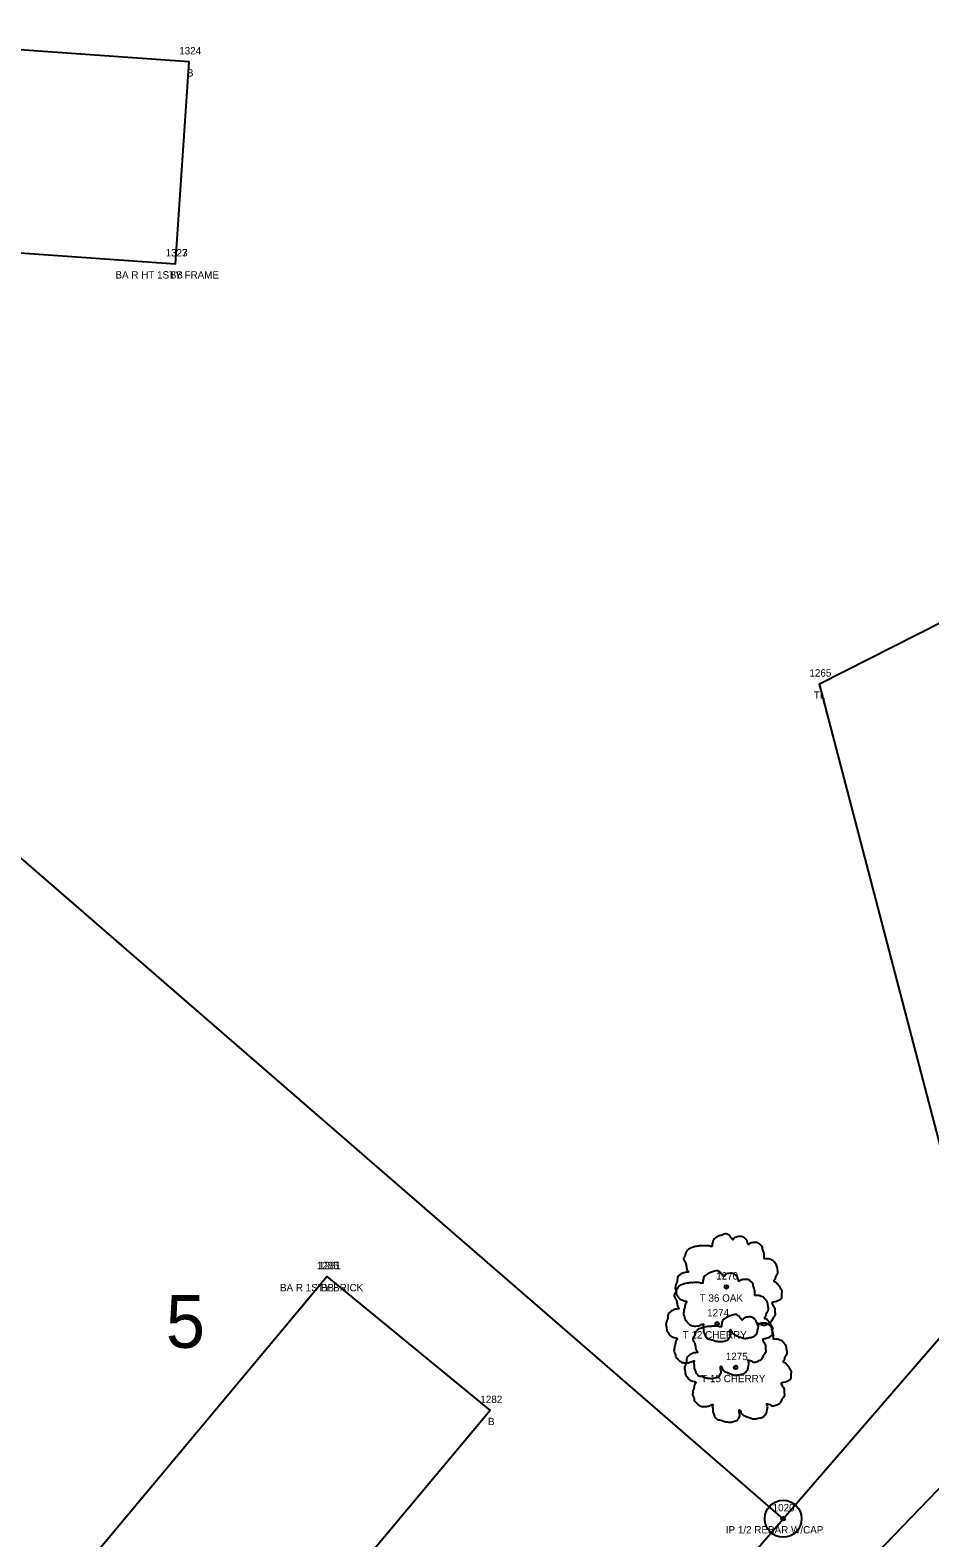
# Model space of a CAD drawing. Extents: x 1812113 to 1819860, y 1177395 to 1181185.
# Drawn here: x 1813774.2 to 1813896.2, y 1178275.6 to 1178480 of the extents above; entities that cross this region are included whole.
import ezdxf

# ---------------------------------------------------------------- set-up
doc = ezdxf.new("R2010")
doc.units = 0
for name, color, linetype in [('RD_EX_Bldg', 7, 'Continuous'), ('RD_EX_Bldg_txCode', 7, 'Continuous'), ('RD_EX_DV_Prop', 7, 'Continuous'), ('RD_EX_DV_Prop_txCode', 7, 'Continuous'), ('RD_EX_DV_PropPin', 7, 'Continuous'), ('RD_EX_DV_TX_Prop', 7, 'Continuous'), ('RD_EX_Road', 7, 'Continuous'), ('RD_EX_VEG', 7, 'Continuous'), ('RD_EX_VEG_txCode', 7, 'Continuous'), ('RD_SMD_Locator', 7, 'Continuous')]:
    doc.layers.add(name, color=color, linetype=linetype)

msp = doc.modelspace()

# ---------------------------------------------------------------- linework, layer by layer
at = {"layer": 'RD_EX_Bldg'}
for points in [[(1813793.91, 1178448.32), (1813795.75, 1178475.7), (1813735.04, 1178479.99), (1813733.19, 1178452.61), (1813793.91, 1178448.32)], [(1813814.41, 1178311.05), (1813836.59, 1178292.91), (1813805.22, 1178255.39), (1813783.05, 1178273.53), (1813814.41, 1178311.05)]]:
    msp.add_lwpolyline(points, dxfattribs=at)
at = {"layer": 'RD_EX_DV_Prop'}
for p, q in [((1813876.31, 1178278.23), (1814007.16, 1178429.49)), ((1813876.31, 1178278.23), (1813762.97, 1178376.42)), ((1813820.68, 1178213.93), (1813876.31, 1178278.23))]:
    msp.add_line(p, q, dxfattribs=at)
at = {"layer": 'RD_EX_DV_PropPin'}
for radius in [2.5, 0.25]:
    msp.add_circle((1813876.31, 1178278.23), radius, dxfattribs=at)
at = {"layer": 'RD_EX_Road'}
msp.add_line((1813874.69, 1178258.74), (1813910.02, 1178295.38), dxfattribs=at)
at = {"layer": 'RD_EX_VEG'}
msp.add_lwpolyline([(1813961.33, 1178431.97), (1813986.04, 1178406.55), (1813953.31, 1178366.71), (1813903.24, 1178307.28), (1813881.24, 1178391.37), (1813961.33, 1178431.97)], dxfattribs=at)
for centre, radius in [((1813868.62, 1178309.64), 0.25), ((1813868.61, 1178309.62), 0.0001), ((1813867.35, 1178304.65), 0.25), ((1813867.34, 1178304.63), 0.0001), ((1813869.87, 1178298.73), 0.25), ((1813869.86, 1178298.71), 0.0001)]:
    msp.add_circle(centre, radius, dxfattribs=at)
for points in [[(1813868.75, 1178316.81), (1813868.45, 1178316.83), (1813868.13, 1178316.73), (1813867.88, 1178316.63), (1813867.65, 1178316.56), (1813867.43, 1178316.46), (1813867.13, 1178316.28), (1813866.9, 1178316.08), (1813866.78, 1178315.83), (1813866.73, 1178315.61), (1813866.68, 1178315.33), (1813866.68, 1178315.16), (1813866.55, 1178315.13), (1813866.4, 1178315.16), (1813866.15, 1178315.23), (1813865.9, 1178315.23), (1813865.65, 1178315.23), (1813865.3, 1178315.21), (1813864.95, 1178315.21), (1813864.68, 1178315.16), (1813864.35, 1178315.11), (1813863.98, 1178314.98), (1813863.63, 1178314.86), (1813863.33, 1178314.61), (1813863.08, 1178314.13), (1813862.96, 1178313.78), (1813862.81, 1178313.53), (1813862.96, 1178313.08), (1813863.13, 1178312.73), (1813863.15, 1178312.53), (1813863.23, 1178312.11), (1813863.33, 1178311.88), (1813863.45, 1178311.68), (1813863.38, 1178311.66), (1813863.01, 1178311.61), (1813862.71, 1178311.51), (1813862.28, 1178311.28), (1813862.06, 1178311.06), (1813861.96, 1178310.73), (1813861.93, 1178310.38), (1813861.83, 1178310.18), (1813861.76, 1178309.91), (1813861.73, 1178309.83), (1813861.68, 1178309.51), (1813861.78, 1178309.06), (1813861.81, 1178308.71), (1813861.93, 1178308.49), (1813862.08, 1178308.31), (1813862.26, 1178308.06), (1813862.66, 1178307.84), (1813862.98, 1178307.74), (1813863.18, 1178307.71), (1813863.01, 1178307.21), (1813862.96, 1178306.86), (1813862.83, 1178306.46), (1813862.83, 1178306.39), (1813862.78, 1178305.91), (1813862.93, 1178305.59), (1813863.01, 1178305.21), (1813863.18, 1178304.99), (1813863.45, 1178304.69), (1813863.78, 1178304.46), (1813864.28, 1178304.34), (1813864.68, 1178304.36), (1813865.25, 1178304.54), (1813865.5, 1178304.61), (1813865.48, 1178304.44), (1813865.5, 1178304.06), (1813865.5, 1178303.64), (1813865.65, 1178303.31), (1813865.75, 1178303.04), (1813865.9, 1178302.79), (1813866.23, 1178302.56), (1813866.63, 1178302.49), (1813867.05, 1178302.34), (1813867.5, 1178302.26), (1813868, 1178302.24), (1813868.6, 1178302.39), (1813868.88, 1178302.51), (1813868.98, 1178302.69), (1813869.18, 1178303.06), (1813869.13, 1178303.29), (1813869.15, 1178303.89), (1813869.25, 1178303.71), (1813869.43, 1178303.36), (1813869.93, 1178303.06), (1813870.33, 1178302.89), (1813870.8, 1178302.74), (1813871.1, 1178302.66), (1813871.58, 1178302.74), (1813871.95, 1178302.81), (1813872.33, 1178302.94), (1813872.63, 1178303.21), (1813872.8, 1178303.49), (1813872.85, 1178303.76), (1813872.93, 1178304.14), (1813872.98, 1178304.31)], [(1813872.98, 1178304.31), (1813872.9, 1178304.49), (1813872.85, 1178304.74), (1813872.93, 1178304.71), (1813873.1, 1178304.66), (1813873.38, 1178304.54), (1813873.6, 1178304.46), (1813873.93, 1178304.49), (1813874.2, 1178304.59), (1813874.65, 1178304.86), (1813874.92, 1178305.34), (1813875.2, 1178305.74), (1813875.27, 1178306.06), (1813875.22, 1178306.29), (1813875.2, 1178306.79), (1813875, 1178307.04), (1813874.95, 1178307.16), (1813874.85, 1178307.56), (1813874.92, 1178307.61), (1813875.2, 1178307.66), (1813875.57, 1178307.79), (1813875.85, 1178307.91), (1813876.07, 1178308.09), (1813876.15, 1178308.31), (1813876.12, 1178308.71), (1813876.17, 1178309.11), (1813876.1, 1178309.26), (1813876, 1178309.41), (1813875.92, 1178309.61), (1813875.77, 1178309.76), (1813875.67, 1178309.91), (1813875.57, 1178310.01), (1813875.45, 1178310.16), (1813875.27, 1178310.28), (1813875.12, 1178310.33), (1813875.07, 1178310.48), (1813875.22, 1178310.68), (1813875.27, 1178310.78), (1813875.3, 1178311.01), (1813875.52, 1178311.36), (1813875.57, 1178311.76), (1813875.52, 1178312.18), (1813875.47, 1178312.46), (1813875.32, 1178312.73), (1813875.12, 1178312.98), (1813875, 1178313.16), (1813874.82, 1178313.28), (1813874.5, 1178313.41), (1813874.25, 1178313.46), (1813873.9, 1178313.46), (1813873.7, 1178313.51), (1813873.73, 1178313.56), (1813873.73, 1178313.71), (1813873.73, 1178313.98), (1813873.65, 1178314.43), (1813873.5, 1178314.93), (1813873.5, 1178314.96), (1813873.4, 1178315.21), (1813873.18, 1178315.41), (1813873, 1178315.51), (1813872.8, 1178315.63), (1813872.55, 1178315.66), (1813872.25, 1178315.66), (1813871.98, 1178315.61), (1813871.78, 1178315.51), (1813871.6, 1178315.38), (1813871.53, 1178315.53), (1813871.43, 1178315.83), (1813871.38, 1178315.98), (1813871.23, 1178316.16), (1813871, 1178316.36), (1813870.55, 1178316.48), (1813869.93, 1178316.41), (1813869.63, 1178316.21), (1813869.48, 1178316.03), (1813869.43, 1178316.16), (1813869.23, 1178316.36), (1813869.13, 1178316.53), (1813868.95, 1178316.66), (1813868.8, 1178316.76), (1813868.7, 1178316.81)], [(1813867.48, 1178311.82), (1813867.18, 1178311.84), (1813866.86, 1178311.74), (1813866.61, 1178311.64), (1813866.38, 1178311.57), (1813866.16, 1178311.47), (1813865.86, 1178311.29), (1813865.63, 1178311.09), (1813865.51, 1178310.84), (1813865.46, 1178310.62), (1813865.41, 1178310.34), (1813865.41, 1178310.17), (1813865.28, 1178310.14), (1813865.13, 1178310.17), (1813864.88, 1178310.24), (1813864.63, 1178310.24), (1813864.38, 1178310.24), (1813864.03, 1178310.22), (1813863.68, 1178310.22), (1813863.41, 1178310.17), (1813863.08, 1178310.12), (1813862.71, 1178309.99), (1813862.36, 1178309.87), (1813862.06, 1178309.62), (1813861.81, 1178309.14), (1813861.68, 1178308.79), (1813861.53, 1178308.54), (1813861.68, 1178308.09), (1813861.86, 1178307.74), (1813861.88, 1178307.54), (1813861.96, 1178307.12), (1813862.06, 1178306.89), (1813862.18, 1178306.69), (1813862.11, 1178306.67), (1813861.73, 1178306.62), (1813861.43, 1178306.52), (1813861.01, 1178306.29), (1813860.78, 1178306.07), (1813860.68, 1178305.74), (1813860.66, 1178305.39), (1813860.56, 1178305.19), (1813860.48, 1178304.92), (1813860.46, 1178304.84), (1813860.41, 1178304.52), (1813860.51, 1178304.07), (1813860.53, 1178303.72), (1813860.66, 1178303.5), (1813860.81, 1178303.32), (1813860.98, 1178303.07), (1813861.38, 1178302.85), (1813861.71, 1178302.75), (1813861.91, 1178302.72), (1813861.73, 1178302.22), (1813861.68, 1178301.87), (1813861.56, 1178301.47), (1813861.56, 1178301.4), (1813861.51, 1178300.92), (1813861.66, 1178300.6), (1813861.73, 1178300.22), (1813861.91, 1178300), (1813862.18, 1178299.7), (1813862.51, 1178299.47), (1813863.01, 1178299.35), (1813863.41, 1178299.37), (1813863.98, 1178299.55), (1813864.23, 1178299.62), (1813864.21, 1178299.45), (1813864.23, 1178299.07), (1813864.23, 1178298.65), (1813864.38, 1178298.32), (1813864.48, 1178298.05), (1813864.63, 1178297.8), (1813864.96, 1178297.57), (1813865.36, 1178297.5), (1813865.78, 1178297.35), (1813866.23, 1178297.27), (1813866.73, 1178297.25), (1813867.33, 1178297.4), (1813867.61, 1178297.52), (1813867.71, 1178297.7), (1813867.91, 1178298.07), (1813867.86, 1178298.3), (1813867.88, 1178298.9), (1813867.98, 1178298.72), (1813868.15, 1178298.37), (1813868.65, 1178298.07), (1813869.05, 1178297.9), (1813869.53, 1178297.75), (1813869.83, 1178297.67), (1813870.3, 1178297.75), (1813870.68, 1178297.82), (1813871.05, 1178297.95), (1813871.35, 1178298.22), (1813871.53, 1178298.5), (1813871.58, 1178298.77), (1813871.65, 1178299.15), (1813871.7, 1178299.32)], [(1813871.7, 1178299.32), (1813871.63, 1178299.5), (1813871.58, 1178299.75), (1813871.65, 1178299.72), (1813871.83, 1178299.67), (1813872.1, 1178299.55), (1813872.33, 1178299.47), (1813872.65, 1178299.5), (1813872.93, 1178299.6), (1813873.38, 1178299.87), (1813873.65, 1178300.35), (1813873.93, 1178300.75), (1813874, 1178301.07), (1813873.95, 1178301.3), (1813873.93, 1178301.8), (1813873.73, 1178302.05), (1813873.68, 1178302.17), (1813873.58, 1178302.57), (1813873.65, 1178302.62), (1813873.93, 1178302.67), (1813874.3, 1178302.8), (1813874.58, 1178302.92), (1813874.8, 1178303.1), (1813874.88, 1178303.32), (1813874.85, 1178303.72), (1813874.9, 1178304.12), (1813874.83, 1178304.27), (1813874.73, 1178304.42), (1813874.65, 1178304.62), (1813874.5, 1178304.77), (1813874.4, 1178304.92), (1813874.3, 1178305.02), (1813874.18, 1178305.17), (1813874, 1178305.29), (1813873.85, 1178305.34), (1813873.8, 1178305.49), (1813873.95, 1178305.69), (1813874, 1178305.79), (1813874.03, 1178306.02), (1813874.25, 1178306.37), (1813874.3, 1178306.77), (1813874.25, 1178307.19), (1813874.2, 1178307.47), (1813874.05, 1178307.74), (1813873.85, 1178307.99), (1813873.73, 1178308.17), (1813873.55, 1178308.29), (1813873.23, 1178308.42), (1813872.98, 1178308.47), (1813872.63, 1178308.47), (1813872.43, 1178308.52), (1813872.45, 1178308.57), (1813872.45, 1178308.72), (1813872.45, 1178308.99), (1813872.38, 1178309.44), (1813872.23, 1178309.94), (1813872.23, 1178309.97), (1813872.13, 1178310.22), (1813871.9, 1178310.42), (1813871.73, 1178310.52), (1813871.53, 1178310.64), (1813871.28, 1178310.67), (1813870.98, 1178310.67), (1813870.7, 1178310.62), (1813870.5, 1178310.52), (1813870.33, 1178310.39), (1813870.25, 1178310.54), (1813870.15, 1178310.84), (1813870.1, 1178310.99), (1813869.95, 1178311.17), (1813869.73, 1178311.37), (1813869.28, 1178311.49), (1813868.65, 1178311.42), (1813868.35, 1178311.22), (1813868.2, 1178311.04), (1813868.15, 1178311.17), (1813867.95, 1178311.37), (1813867.86, 1178311.54), (1813867.68, 1178311.67), (1813867.53, 1178311.77), (1813867.43, 1178311.82)], [(1813870.01, 1178305.89), (1813869.71, 1178305.92), (1813869.38, 1178305.82), (1813869.13, 1178305.72), (1813868.91, 1178305.64), (1813868.68, 1178305.54), (1813868.38, 1178305.37), (1813868.16, 1178305.17), (1813868.03, 1178304.92), (1813867.98, 1178304.69), (1813867.93, 1178304.42), (1813867.93, 1178304.25), (1813867.81, 1178304.22), (1813867.66, 1178304.25), (1813867.41, 1178304.32), (1813867.16, 1178304.32), (1813866.91, 1178304.32), (1813866.56, 1178304.3), (1813866.21, 1178304.3), (1813865.93, 1178304.25), (1813865.61, 1178304.2), (1813865.23, 1178304.07), (1813864.88, 1178303.95), (1813864.58, 1178303.7), (1813864.33, 1178303.22), (1813864.21, 1178302.87), (1813864.06, 1178302.62), (1813864.21, 1178302.17), (1813864.38, 1178301.82), (1813864.41, 1178301.62), (1813864.48, 1178301.2), (1813864.58, 1178300.97), (1813864.71, 1178300.77), (1813864.63, 1178300.75), (1813864.26, 1178300.7), (1813863.96, 1178300.6), (1813863.53, 1178300.37), (1813863.31, 1178300.15), (1813863.21, 1178299.82), (1813863.18, 1178299.47), (1813863.08, 1178299.27), (1813863.01, 1178299), (1813862.98, 1178298.92), (1813862.93, 1178298.6), (1813863.03, 1178298.15), (1813863.06, 1178297.8), (1813863.18, 1178297.57), (1813863.33, 1178297.4), (1813863.51, 1178297.15), (1813863.91, 1178296.92), (1813864.23, 1178296.82), (1813864.43, 1178296.8), (1813864.26, 1178296.3), (1813864.21, 1178295.95), (1813864.08, 1178295.55), (1813864.08, 1178295.47), (1813864.03, 1178295), (1813864.18, 1178294.67), (1813864.26, 1178294.3), (1813864.43, 1178294.07), (1813864.71, 1178293.77), (1813865.03, 1178293.55), (1813865.53, 1178293.42), (1813865.93, 1178293.45), (1813866.51, 1178293.62), (1813866.76, 1178293.7), (1813866.73, 1178293.52), (1813866.76, 1178293.15), (1813866.76, 1178292.73), (1813866.91, 1178292.4), (1813867.01, 1178292.13), (1813867.16, 1178291.88), (1813867.48, 1178291.65), (1813867.88, 1178291.58), (1813868.31, 1178291.43), (1813868.76, 1178291.35), (1813869.26, 1178291.33), (1813869.86, 1178291.48), (1813870.13, 1178291.6), (1813870.23, 1178291.78), (1813870.43, 1178292.15), (1813870.38, 1178292.38), (1813870.41, 1178292.98), (1813870.51, 1178292.8), (1813870.68, 1178292.45), (1813871.18, 1178292.15), (1813871.58, 1178291.98), (1813872.05, 1178291.83), (1813872.35, 1178291.75), (1813872.83, 1178291.83), (1813873.2, 1178291.9), (1813873.58, 1178292.03), (1813873.88, 1178292.3), (1813874.05, 1178292.58), (1813874.1, 1178292.85), (1813874.18, 1178293.22), (1813874.23, 1178293.4)], [(1813874.23, 1178293.4), (1813874.15, 1178293.57), (1813874.1, 1178293.82), (1813874.18, 1178293.8), (1813874.35, 1178293.75), (1813874.63, 1178293.62), (1813874.85, 1178293.55), (1813875.18, 1178293.57), (1813875.45, 1178293.67), (1813875.9, 1178293.95), (1813876.18, 1178294.42), (1813876.45, 1178294.82), (1813876.53, 1178295.15), (1813876.48, 1178295.37), (1813876.45, 1178295.87), (1813876.25, 1178296.12), (1813876.2, 1178296.25), (1813876.1, 1178296.65), (1813876.18, 1178296.7), (1813876.45, 1178296.75), (1813876.83, 1178296.87), (1813877.1, 1178297), (1813877.33, 1178297.17), (1813877.4, 1178297.4), (1813877.38, 1178297.8), (1813877.43, 1178298.2), (1813877.35, 1178298.35), (1813877.25, 1178298.5), (1813877.18, 1178298.7), (1813877.03, 1178298.85), (1813876.93, 1178299), (1813876.83, 1178299.1), (1813876.7, 1178299.25), (1813876.53, 1178299.37), (1813876.38, 1178299.42), (1813876.33, 1178299.57), (1813876.48, 1178299.77), (1813876.53, 1178299.87), (1813876.55, 1178300.1), (1813876.78, 1178300.45), (1813876.83, 1178300.85), (1813876.78, 1178301.27), (1813876.73, 1178301.55), (1813876.58, 1178301.82), (1813876.38, 1178302.07), (1813876.25, 1178302.25), (1813876.08, 1178302.37), (1813875.75, 1178302.5), (1813875.5, 1178302.55), (1813875.15, 1178302.55), (1813874.95, 1178302.6), (1813874.98, 1178302.65), (1813874.98, 1178302.8), (1813874.98, 1178303.07), (1813874.9, 1178303.52), (1813874.75, 1178304.02), (1813874.75, 1178304.05), (1813874.65, 1178304.3), (1813874.43, 1178304.5), (1813874.25, 1178304.59), (1813874.05, 1178304.72), (1813873.8, 1178304.74), (1813873.5, 1178304.74), (1813873.23, 1178304.69), (1813873.03, 1178304.59), (1813872.85, 1178304.47), (1813872.78, 1178304.62), (1813872.68, 1178304.92), (1813872.63, 1178305.07), (1813872.48, 1178305.24), (1813872.25, 1178305.44), (1813871.8, 1178305.57), (1813871.18, 1178305.49), (1813870.88, 1178305.29), (1813870.73, 1178305.12), (1813870.68, 1178305.24), (1813870.48, 1178305.44), (1813870.38, 1178305.62), (1813870.21, 1178305.74), (1813870.06, 1178305.84), (1813869.96, 1178305.89)]]:
    msp.add_spline(points, degree=3, dxfattribs=at)
at = {"layer": 'RD_SMD_Locator'}
for centre in [(1813795.75, 1178475.7), (1813793.91, 1178448.32), (1813793.91, 1178448.32), (1813881.24, 1178391.37), (1813814.41, 1178311.05), (1813814.41, 1178311.05), (1813836.59, 1178292.91)]:
    msp.add_circle(centre, 0.001, dxfattribs=at)

# ---------------------------------------------------------------- texts
at = {"layer": 'RD_EX_Bldg_txCode'}
for s, p in [('1324', (1813794.41, 1178476.7)), ('B', (1813795.45, 1178473.7)), ('1323', (1813792.56, 1178449.32)), ('1327', (1813792.56, 1178449.32)), ('BA R HT 1STY FRAME', (1813785.76, 1178446.32)), ('BB', (1813793.13, 1178446.32)), ('1285', (1813813.07, 1178312.05)), ('1281', (1813813.35, 1178312.05)), ('BA R 1STY BRICK', (1813808.07, 1178309.05)), ('BB', (1813813.63, 1178309.05)), ('1282', (1813835.24, 1178293.91)), ('B', (1813836.28, 1178290.91))]:
    msp.add_text(s, height=1, dxfattribs=at).set_placement(p)
at = {"layer": 'RD_EX_DV_Prop_txCode'}
for s, p in [('1020', (1813874.88, 1178279.23)), ('IP 1/2 REBAR W/CAP', (1813868.53, 1178276.23))]:
    msp.add_text(s, height=1, dxfattribs=at).set_placement(p)
at = {"layer": 'RD_EX_DV_TX_Prop'}
msp.add_text('5', height=7.14, dxfattribs=at).set_placement((1813792.6, 1178301.39))
at = {"layer": 'RD_EX_VEG_txCode'}
for s, p in [('1265', (1813879.87, 1178392.37)), ('TL', (1813880.47, 1178389.37)), ('1270', (1813867.23, 1178310.64)), ('T 36 OAK', (1813864.99, 1178307.64)), ('1274', (1813866, 1178305.65)), ('T 12 CHERRY', (1813862.68, 1178302.65)), ('1275', (1813868.53, 1178299.73)), ('T 15 CHERRY', (1813865.2, 1178296.73))]:
    msp.add_text(s, height=1, dxfattribs=at).set_placement(p)

doc.saveas('drawing.dxf')
